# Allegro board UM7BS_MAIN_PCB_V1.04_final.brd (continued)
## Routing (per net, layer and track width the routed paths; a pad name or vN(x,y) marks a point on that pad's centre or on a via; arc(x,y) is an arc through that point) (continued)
GL850G_X1: length 7
  TOP w0.102: U9.6 180.29,89.43 C155.2 180.67,89.13 181.09,89.54 183.73,89.54 183.73,89.54 X4.1
GL850G_X2: length 5.4
  TOP w0.102: X4.3 182.97,90.21 182.51,89.75 181.1,89.75 C154.2 180.58,90.08 U9.7
GP_CAMERASB08: length 20.4
  TOP w0.102: U1.Y44 181.11,70.94 v1(180.74,71.31)
  LAY3 w0.102: v1(180.74,71.31) 180.36,71.69 180.36,74.18 181.63,75.45 181.63,76.22 182.38,76.97 182.38,77.92 188.13,83.67 v1(188.13,86.91)
  BOTTOM w0.152: R230.2 187.79,86.57 v1(188.13,86.91)
GP_CAMERASB09: length 23.7
  TOP w0.102: R228.1 188.22,88.44 189.28,87.38 189.28,86.69 188.98,86.39 v1(188.56,86.39) ; v1(180.74,70.68) 181.19,70.23 U1.Y42
  LAY3 w0.102: v1(188.56,86.39) 188.56,83.8 182.57,77.82 182.57,75.63 181.19,74.25 181.19,71.13 v1(180.74,70.68)
  BOTTOM w0.102: R232.2 181,70.94 v1(180.74,70.68)
GP_CAMERASB11: length 24.7
  TOP w0.102: v1(188.8,87) 188.8,87.53 188.4,87.93 R233.2 R229.1 ; U1.V40 180.27,68.8 v1(180.61,69.15)
  LAY3 w0.102: v1(188.8,87) 188.96,86.84 188.96,83.9 182.76,77.71 182.76,75.55 181.38,74.17 181.38,69.91 v1(180.61,69.15)
GPIO_SUS8: length 11.8
  TOP w0.102: 184.2,76.94 184.42,76.72 184.42,75.64 184.36,75.58 184.36,75.26 184.45,75.18 184.45,74.9 184.15,74.6 U1.AF51
  TOP w0.114: R68.1 182.69,84.34 182.3,83.95 182.3,82.48 R77.2 183.29,81.49 183.29,77.85 184.2,76.94
GPIO_SUS9: length 10.7
  TOP w0.102: U1.AF52 184.16,75.04 184.16,75.67 184.22,75.73 184.22,76.51 184,76.73
  TOP w0.114: 184,76.73 181.83,78.9 R76.1 181.27,82.57 181.27,83.69 R67.1
GPIO_SUS10: length 9.1
  TOP w0.102: 183.82,76.49 184.01,76.29 184.01,75.81 183.95,75.75 183.95,75.28 183.95,75.28 183.95,75.26 183.8,75.11 183.8,74.81 U1.AE51
  TOP w0.114: 183.82,76.49 181.29,79.02 181.29,80.95 R75.1 179.95,81.51 R66.2
GPIO_SUS11: length 7.5
  TOP w0.102: 182.29,76.3 182.39,76.2 182.39,75.27 182.7,74.96 U1.AC51
  TOP w0.114: 182.29,76.3 182.29,76.36 180.72,77.93 179.94,77.93 178.37,79.5 R78.2
GPO: length 2.7
  BOTTOM w0.114: R317.2 124.23,34.28 123.47,35.05 122.99,35.05 122.73,35.3 U22.38
H_PROCHOT#: length 145.4
  TOP w0.102: U33.4 51.04,64.6 C428.1 52.85,65.97 v1(53.48,66.6)
  TOP w0.114: U1.AD50 183.2,73.62 182.94,73.88 v1(182.75,73.88)
  LAY3 w0.102: v1(153.25,75.21) 151.12,77.34 112.64,77.34 111.22,75.92 103.19,75.92 101.38,74.1 80.25,74.1 79.38,74.97 73.85,74.97 v1(72.06,73.18)
  LAY4 w0.102: v1(53.48,66.6) 58.13,71.25 60.63,71.25 61.65,72.26 71.15,72.26 v1(72.06,73.18)
  BOTTOM w0.102: R108.1 182.25,75.1 180.62,75.1 180.12,75.61 175.86,75.61 174.65,76.82 174.65,78.36 173.67,79.33 169.88,79.33 169.14,78.59 158.91,78.59 155.52,75.21 v1(153.25,75.21)
  BOTTOM w0.114: R108.1 182.87,74 v1(182.75,73.88)
H_RCIN#: length 16.5
  TOP w0.102: v1(68.41,69.41) 69.56,68.25 72.21,68.25 73.08,69.12 74.66,69.12 v1(75.01,68.77)
  TOP w0.114: v1(75.01,68.77) 75.47,68.31 76.11,68.31 76.57,68.77 R412.2
  BOTTOM w0.102: v1(68.41,69.41) 67.79,70.02 D11.P
  BOTTOM w0.114: v1(75.01,68.77) 75.27,68.51 R414.1 75.55,68.13 76.06,67.63 U30.9 ; R431.1 65.87,70.79 66.64,70.02 D11.P
HD: length 35.9
  TOP w0.102: v1(179.6,47.56) 179.99,47.96 179.99,49.56 180.06,49.63 180.06,49.95 179.9,50.12 179.9,50.42 U1.U3
  TOP w0.114: v1(163.2,43.13) 161.8,44.53 161.8,48.79 160.98,49.61 158.11,49.61 v1(157.8,49.29) 157.84,49.25 U2.7 U4.7
  BOTTOM w0.102: v1(157.8,49.29) 157.67,49.17 R41.1
  BOTTOM w0.114: v1(163.2,43.13) 164.08,43.13 164.82,42.39 172.04,42.39 174.08,44.43 175.11,44.43 176.91,46.23 176.91,46.69 177.79,47.56 v1(179.6,47.56)
HDA_BITCLK: length 170.4
  TOP w0.114: v1(182.02,46.39) 181.31,45.68 180.73,45.68 177.88,42.83 166.32,42.83 165.36,43.78 165.36,44.8 163.75,46.41 163.75,49.09 161.52,51.33 159.82,51.33 158.89,52.26 156.22,52.26 155.17,51.21 126.69,51.21 124.86,49.39 115.52,49.39 112.66,46.53 110.39,46.53 109.41,45.55 100.37,45.55 98.56,43.74 93.39,43.74 87.94,38.29 81.01,38.29 80.76,38.03 66.36,38.03 64.37,36.04 42.45,36.04 42.22,36.28 33.2,36.28 32.6,35.68 v1(30.31,35.68)
  BOTTOM w0.114: v1(182.02,46.39) R31.2 ; v1(30.31,35.68) C389.2 29.67,35.04 U25.6
HDA_RST#: length 176.7
  TOP w0.102: v1(28.24,32.12) 28.24,32.14 29.29,33.19 30.59,33.19
  TOP w0.114: v1(183.35,45.78) 182.67,45.09 182.67,44.81 182.29,44.44 181.26,44.44 179.94,43.11 179.94,42.9 179.01,41.97 165.85,41.97 163.36,44.46 163.36,45.58 162.57,46.37 162.57,49.05 161.17,50.46 156.78,50.46 156.61,50.28 127.43,50.28 125.46,48.31 117.83,48.31 115.19,45.67 111.03,45.67 108.24,42.88 94.29,42.88 88.83,37.42 81.37,37.42 81.12,37.17 66.72,37.17 64.61,35.06 41.63,35.06 v1(41.5,35.2) 34.48,35.2 32.79,33.5 30.9,33.5 30.59,33.19
  BOTTOM w0.102: R358.1 39.98,37.53 40.44,37.08 R359.2 41.23,36.68 41.5,36.41 v1(41.5,35.2)
  BOTTOM w0.114: R30.2 v1(183.35,45.78) ; v1(28.24,32.12) 28.33,32.21 28.33,32.73 28.01,33.04 U25.11
HDA_SDATAIN0: length 175.2
  TOP w0.114: v1(181.87,45.55) 181.87,45.39 181.66,45.18 180.93,45.18 178.09,42.33 166.09,42.33 164.81,43.62 164.81,44.65 162.95,46.51 162.95,49.2 161.31,50.83 159.61,50.83 158.71,51.74 156.52,51.74 155.43,50.65 127.05,50.65 125.15,48.76 116.18,48.76 113.46,46.04 110.66,46.04 107.87,43.25 93.6,43.25 88.14,37.79 81.22,37.79 80.96,37.54 66.56,37.54 64.57,35.55 42.17,35.55 41.95,35.76 33.87,35.76 v1(32.57,34.47)
  BOTTOM w0.114: R32.2 181.4,49.41 181.4,46.02 v1(181.87,45.55) ; v1(32.57,34.47) 32.44,34.33 C391.2 31.89,33.37 29.54,33.37 28.67,34.24 U25.8
HDA_SDATAOUT: length 171.1
  TOP w0.114: v1(29.94,36.77) 42.47,36.77 42.7,36.54 64.16,36.54 66.15,38.53 80.55,38.53 80.81,38.78 87.73,38.78 93.18,44.24 95.7,44.24 98.58,47.12 99.46,47.12 100.53,46.05 109.11,46.05 110.1,47.04 112.46,47.04 115.37,49.94 124.62,49.94 126.4,51.72 154.92,51.72 155.97,52.77 159.07,52.77 160.02,51.82 161.72,51.82 164.3,49.25 164.3,46.57 167.54,43.32 177.68,43.32 180.53,46.18 181.1,46.18 181.96,47.03 v1(182.58,47.03)
  BOTTOM w0.114: v1(29.94,36.77) C392.2 29.11,35.44 U25.5 ; v1(182.58,47.03) 182.83,47.28 R34.2
HDA_SYNC: length 178.2
  TOP w0.102: 94.8,42.51 108.76,42.51 111.54,45.29 115.61,45.29 118.18,47.86 125.59,47.86 127.65,49.91 156.86,49.91
  TOP w0.114: 94.8,42.51 89.34,37.06 81.52,37.06 81.27,36.8 67.01,36.8 63.57,33.36 35.57,33.36 34.36,32.16 v1(34.36,31.65) ; v1(183.36,44.96) 183.36,44.93 180.43,42 179.78,42 179.38,41.6 165.59,41.6 162.98,44.21 162.98,45.41 162.18,46.21 162.18,48.93 161.02,50.09 157.03,50.09 156.86,49.91
  BOTTOM w0.114: U25.10 28.11,33.44 28.71,32.84 28.71,31.65 29.89,30.47 33.89,30.47 C390.2 34.36,30.59 v1(34.36,31.65) ; R33.2 184.94,45.04 184.7,44.79 183.53,44.79 v1(183.36,44.96)
HP_OUT_L: length 8.9
  TOP w0.305: R352.2 21.92,29.07 R356.1 21.92,29.38 C396.1 21.89,30.15 18.5,33.54 18.5,34.72 v1(18.34,34.88)
  BOTTOM w0.305: R332.1 18.35,34.89 v1(18.34,34.88)
HP_OUT_R: length 11.9
  TOP w0.305: v1(18.4,35.71) 18.93,35.19 18.93,33.81 21.29,31.44 22.75,31.44 23.86,30.33 R357.1 24.65,29.65 C397.1 24.82,29.66 R354.2
  BOTTOM w0.305: v1(18.4,35.71) 18.53,35.71 18.54,35.71 R331.1
HSON: length 4.6
  BOTTOM w0.124: U22.23 122.73,42.03 122.66,42.1 122.66,42.23 122.74,42.32 124.48,42.32 124.93,42.77 124.93,43.65 C346.2
HSOP: length 4.6
  BOTTOM w0.124: C347.2 124.68,43.65 124.68,42.87 124.38,42.57 122.64,42.57 122.4,42.34 122.4,42.1 122.33,42.03 U22.22
HUB_USB_PN1: length 131.5
  TOP w0.112: U9.2 v1(179.51,86.83)
  TOP w0.124: CN26.5 240.92,27.77 v1(241.03,27.67)
  LAY3 w0.112: v1(179.51,86.83) 179.51,86.92 179.83,87.24 181.45,87.24 187.15,92.94 195.48,92.94 199.62,97.08 203.74,97.08 205.57,98.91 210.39,98.91 212.47,100.98 213.53,100.98 214.06,100.46 218.66,100.46 227.42,91.7 227.42,47.79 240.1,35.11 240.1,28.06 240.41,27.75 240.95,27.75 v1(241.03,27.67)
HUB_USB_PN2: length 101.9
  TOP w0.124: v1(165.55,86.8) 165.73,86.63 170.77,86.63 170.97,86.83 U9.27
  LAY3 w0.112: v1(165.55,86.8) 165.34,86.6 163.53,86.6 158.88,91.24 151.87,91.24 149.31,93.8 119.31,93.8 117.44,91.92 111.64,91.92 110.97,91.25 96.33,91.25 95.26,92.32 85.85,92.32 82.92,95.26 77.44,95.26 v1(77.27,95.43)
  BOTTOM w0.124: v1(77.27,95.43) 77.1,95.25 76.7,95.25 76.58,95.37 U95.2
HUB_USB_PP1: length 131.6
  TOP w0.112: U9.3 179.49,87.48 v1(179.49,87.48)
  TOP w0.124: v1(241.03,28.28) 240.78,28.02 239.36,28.02 239.11,28.27 CN26.3
  LAY3 w0.112: v1(179.49,87.48) 181.35,87.48 187.05,93.18 195.38,93.18 199.52,97.32 203.64,97.32 205.47,99.15 210.29,99.15 212.37,101.22 213.63,101.22 214.16,100.7 218.75,100.7 227.66,91.8 227.66,47.89 240.34,35.21 240.34,28.16 240.51,27.99 240.74,27.99 v1(241.03,28.28)
HUB_USB_PP2: length 101.9
  TOP w0.124: v1(165.57,86.15) 165.8,86.38 170.77,86.38 170.97,86.18 U9.28
  LAY3 w0.112: v1(77.27,94.85) 77.44,95.02 82.82,95.02 85.75,92.09 95.16,92.09 96.23,91.02 111.07,91.02 111.74,91.69 117.54,91.69 119.41,93.56 149.21,93.56 151.77,91 158.78,91 163.43,86.36 165.36,86.36 v1(165.57,86.15)
  BOTTOM w0.124: U95.3 76.58,94.87 76.7,95 77.13,95 v1(77.27,94.85)
I2C_CLK0: length 2.9
  BOTTOM w0.114: R401.2 51.84,74.09 53.13,72.81 U31.110
I2C_CLK1: length 5.4
  BOTTOM w0.127: R423.2 54.38,76.05 54.38,74.63 R396.2 55.25,73.76 55.25,72.72 55.13,72.59 U31.115
I2C_CLK2: length 2.8
  BOTTOM w0.114: U31.117 55.93,72.46 56.92,73.45 R405.2
I2C_CLK2_LVDS: length 117.2
  LAY3 w0.127: v1(152.66,81.76) 152.16,81.25 123.29,81.25 122.13,82.4 116.5,82.4 115.74,83.17 58.31,83.17 54.89,79.75 v1(54.89,78.26)
  BOTTOM w0.102: U16.25 151.11,92.27 150.56,91.72 150.56,88.74 151.87,87.43 152.3,87.43 152.9,86.83 152.9,86.46 R276.2 152.66,85.75 153.06,85.35 153.06,82.16 v1(152.66,81.76) 152.03,82.4 U18.6
  BOTTOM w0.127: v1(54.89,78.26) 54.86,78.23 R423.1
I2C_CLK3: length 2.4
  BOTTOM w0.127: U31.94 45.43,69.46 44.95,69.94 R392.2
I2C_DATA0: length 2.7
  BOTTOM w0.114: U31.111 53.53,73.04 52.86,73.71 R402.2
I2C_DATA1: length 5.4
  BOTTOM w0.127: R424.2 55.4,76.09 55.4,74.63 R399.2 55.9,72.93 55.53,72.55 U31.116
I2C_DATA2: length 3.3
  BOTTOM w0.114: R408.2 57.94,73.58 57.75,73.4 57.41,73.4 56.33,72.32 U31.118
I2C_DATA2_LVDS: length 117.2
  LAY3 w0.127: v1(55.84,78.21) 55.84,80.1 58.62,82.87 115.53,82.87 116.25,82.16 121.77,82.16 123.31,80.62 145.95,80.62 146.35,80.22 151.75,80.22 v1(152.66,81.13)
  BOTTOM w0.102: U18.5 v1(152.66,81.13) 153.5,81.97 R277.2 153.25,86.47 153.25,86.86 152.41,87.69 151.98,87.69 150.82,88.85 150.82,91.61 151.51,92.29 U16.24
  BOTTOM w0.127: R424.1 55.84,78.21 v1(55.84,78.21)
I2C_DATA3: length 2.5
  BOTTOM w0.127: U31.95 45.69,69.86 44.82,70.73 R394.2
IINA: length 5.9
  BOTTOM w0.406: CN22.2 107.26,96.95 106.35,97.87 R3103.1 R3104.1 R3101.1 R3102.1
IINA0: length 26.6
  LAY3 w0.406: v1(113.26,95.59) 113.26,95.38 112.87,94.99 107.92,94.99 106.76,96.15 v1(103.73,96.15)
  BOTTOM w0.406: R3101.2 v1(103.73,96.15) ; v1(113.26,95.59) J5.1 115.85,94.33 R345.1 115.94,94.25 118.08,94.25 124.18,88.15 U41.1
IINA1: length 29.1
  LAY3 w0.406: v1(102.88,96.16) 103.43,96.71 107.13,96.71 108.25,95.59 v1(112.63,95.59)
  BOTTOM w0.406: R3102.2 v1(102.88,96.16) ; v1(112.63,95.59) 112.26,95.22 J5.2 112.26,93.52 112.75,93.03 115.5,93.03 R345.2 116.2,93.73 117.65,93.73 123.88,87.5 U41.2
IINA2: length 29.5
  LAY3 w0.406: v1(106.19,95.1) 107.44,93.84 113.89,93.84 114.86,94.81 v1(116.78,94.81)
  BOTTOM w0.406: U41.4 125.94,86.2 126.33,86.6 R3089.1 126.33,87.54 126.08,87.79 126.08,88.53 125.52,89.09 124.15,89.09 118.44,94.81 v1(116.78,94.81) ; v1(106.19,95.1) R367.2 R3095.1 105.56,96.82 R3103.2
IINA3: length 37
  LAY3 w0.406: v1(103.79,95.1) 104.33,95.64 106.4,95.64 107.59,94.45 113.66,94.45 114.59,95.38 v1(116.85,95.38)
  BOTTOM w0.406: v1(116.85,95.38) 118.96,95.38 124.55,89.78 126.8,89.78 128.16,88.42 R3090.1 128.16,85.8 127.92,85.55 U41.5 ; R3104.2 104.61,96.91 R3095.2 104.62,95.93 R3097.2 v1(103.79,95.1)
INNER_MIC: length 53.2
  TOP w0.305: B1.1 57.54,8.91 CN7.2 54.51,10.4 52.02,7.9 33.42,7.9 25.82,15.5 25.82,26.18 25.53,26.48 v1(25.53,26.79)
  BOTTOM w0.305: v1(25.53,26.79) 25.88,27.14 R333.2 25.7,27.69 C377.1 C373.1
IRQB: length 171
  TOP w0.102: R407.2 78.79,62.71 v1(79.08,63.01) ; Q52.2 151.5,16.75 v1(151.09,17.16)
  LAY3 w0.102: v1(149.48,59.71) 149.11,60.07 147.28,60.07 146.85,60.5 146.85,62.12 136.1,72.88 128.11,72.88 127.91,72.68 119.18,72.68 118.08,71.58 118.08,67.67 114.26,63.85 80.4,63.85 79.56,63.01 v1(79.08,63.01)
  LAY4 w0.102: v1(149.48,59.71) 149.25,59.47 149.25,52.69 153.58,48.36 154.07,48.36 155.2,47.22 v1(155.2,41.42) 155.2,40.61 155.59,40.23 155.59,36.45 158.25,33.79 158.25,28.6 158.49,28.37 158.49,26.84 158.21,26.56 158.21,19.84 156.95,18.58 155.1,18.58 154.43,19.25 151.79,19.25 151.09,18.55 v1(151.09,17.16)
  BOTTOM w0.102: v1(79.08,63.01) 78.93,63.16 U32.4
  BOTTOM w0.114: R569.1 180.75,50.03 178.8,48.08 177.59,48.08 176.45,46.94 176.45,46.51 175.43,45.49 174.34,45.49 171.76,42.91 165.21,42.91 164.28,43.84 161.3,43.84 159.7,42.24 156.02,42.24 v1(155.2,41.42)
ISETA: length 37.6
  TOP w0.305: 110.11,85.12 109.36,84.37 109.36,83.81 110.05,83.12 110.06,83.12 ; 110.11,85.12 CN40.6 112.61,85.12 R466.2 112.61,84.55 113.11,84.05 120.94,84.05 121.54,83.46 122.28,83.46 123.59,84.77 v1(126,84.77) ; 110.11,85.12 109.26,85.97 109.26,86.48 109.89,87.12 CN40.8 112.61,87.12 R3099.2 ; R465.2 111.11,83.11 CN40.4 110.06,83.12 ; R3098.2 111.11,81.11 CN40.2 110.02,81.12 109.35,81.79 109.35,82.4 110.06,83.12
  BOTTOM w0.305: R648.1 R638.2 R754.1 126.42,84.77 v1(126,84.77) 125.85,84.77 125.72,84.9 U41.6
ISOLATEB: length 3.2
  BOTTOM w0.114: R307.1 R305.1 125.37,40.89 124.89,40.4 U22.26
ISW: length 1.9
  BOTTOM w0.305: U41.10 118.05,84.25 117.39,83.6 R3091.2
IT8928_VSS: length 4.1
  BOTTOM w0.114: R452.1 49.59,72.7 50.57,72.7 50.73,72.54 U31.104
KBC_FAN_SPEED: length 107.7
  TOP w0.203: C1.2 129.67,10.1 Q1.3 ; C1.2 R584.2 ; C1.2 v1(129.67,13.76)
  LAY4 w0.102: v1(56.33,52.89) 62.15,52.89 63.39,54.14 64.12,54.14 66.31,51.95 94.32,51.95 96.9,49.37 105.6,49.37 107.73,47.24 107.73,39.92 108.66,38.99 108.66,35.98 110.04,34.6 111.55,34.6 119.14,27.01 119.14,18.23 121.24,16.13 127.02,16.13 129.39,13.76 v1(129.67,13.76)
  BOTTOM w0.102: R435.1 55.79,53.43 v1(56.33,52.89)
L_OUT+: length 7.5
  TOP w0.508: R362.1 242.16,14.64 242.75,15.22 242.75,16.75 242.26,17.24 CN10.2
L_OUT-: length 5
  TOP w0.508: CN10.1 240.94,15.6 R363.1
LAN_CMT: length 2
  TOP w0.406: R322.2 95.71,37.79 U23.11
LAN_CMT1: length 1.8
  BOTTOM w0.406: U24.11 95.92,35.24 R325.2
LAN_CT: length 1.7
  TOP w0.406: R321.2 95.99,33.98 U23.14
LAN_CT1: length 2
  BOTTOM w0.406: R323.2 95.71,39.05 U24.14
LAN_N1: length 23.6
  TOP w0.305: v1(92.47,35.78) 90.77,35.78 v1(90.27,35.28)
  TOP w0.406: R321.1 v1(95.04,34.59) 95.04,35.34 95.71,36 R322.1
  TOP w0.508: v1(95.93,21.99) 95.93,19.26 v1(95.97,19.22)
  BOTTOM w0.305: v1(92.47,35.78) R328.2 93.36,34.39 ; v1(90.27,35.28) 89.97,35.28 89.73,35.04 R329.2 ; R324.2 v1(95.97,19.22)
  BOTTOM w0.406: 95.71,36.83 R323.1
  BOTTOM w0.508: 95.25,28.53 96.53,27.25 96.53,22.48 96.05,21.99 v1(95.93,21.99) R327.2 ; 95.71,36.83 94.97,36.09 R325.1
LAN_TX0N: length 11.9
  TOP w0.102: U23.9 95.84,40.33 93.37,37.85 93.37,35.63 92.49,34.75 91.12,34.75 90.58,34.21 90.58,33.46 FIL1.1
LAN_TX0P: length 12.7
  TOP w0.102: FIL1.4 90.88,33.88 90.88,34.09 91.25,34.45 92.61,34.45 93.67,35.5 93.67,37.73 95.96,40.03 96.15,40.03 96.3,39.88 96.3,38.98 96.44,38.84 97.44,38.84 U23.10
LAN_TX1N: length 2.3
  TOP w0.102: FIL2.1 96.01,32.22 96.58,32.22 97.06,32.71 U23.15
LAN_TX1P: length 2.3
  TOP w0.102: FIL2.4 96.02,31.92 96.54,31.92 97.02,31.44 U23.16
LAN_TX2N: length 18
  BOTTOM w0.102: FIL3.4 94.46,21.04 R327.1 95.66,20.77 97.06,20.77 99.44,23.15 99.44,32.92 99.17,33.19 98.78,33.19 98.29,32.7 U24.9
LAN_TX2P: length 19
  BOTTOM w0.102: U24.10 98.3,33.97 98.78,33.49 99.29,33.49 99.74,33.04 99.74,23.03 97.18,20.47 95.67,20.47 R324.1 94.48,20.17 FIL3.1
LAN_TX3N: length 11.6
  BOTTOM w0.102: U24.15 97.04,40.32 96.56,40.81 95.95,40.81 91.25,36.11 91.25,34.66 R328.1 91.23,34.1 91.23,33.84 FIL4.1
LAN_TX3P: length 12.1
  BOTTOM w0.102: U24.16 97.06,41.59 96.58,41.11 95.83,41.11 90.95,36.23 90.95,34.67 R329.1 90.93,34.15 90.93,33.8 FIL4.4
LAN_VDDEN_EC: length 79.4
  LAY4 w0.102: v1(63.7,53.6) 65.64,51.66 94.15,51.66 96.66,49.15 105.53,49.15 107.53,47.15 107.53,39.69 108.36,38.86 108.36,35.76 109.3,34.82 109.3,33.97 v1(115.68,27.58)
  BOTTOM w0.102: R301.2 U21.3 114.67,28.15 115.23,27.58 v1(115.68,27.58)
  BOTTOM w0.114: U31.29 62.64,59.06 63.36,58.34 63.36,53.94 v1(63.7,53.6)
LANWAKEB: length 4.5
  BOTTOM w0.114: R304.1 128.21,39.49 125.12,39.49 125.01,39.6 U22.28
LAO1_CLKN: length 26
  BOTTOM w0.124: CN35.8 134.91,95.04 134.61,94.74 134.41,94.74 134.17,94.49 134.17,93.79 133.89,93.52 133.07,93.52 132.97,93.42 132.97,93.17 133.11,93.03 133.89,93.03 134.17,92.75 134.17,92.3 133.89,92.02 133.42,92.02 133.29,91.9 133.29,91.65 133.42,91.53 133.89,91.53 134.17,91.26 134.17,90.89 134.41,90.65 137.98,90.65 138.96,91.63 144.01,91.63 148.28,95.89 148.63,95.89 148.7,95.97 U16.35
LAO1_CLKP: length 26
  BOTTOM w0.124: CN35.9 133.91,93.9 133.79,93.77 132.97,93.77 132.71,93.52 132.71,93.06 133,92.77 133.79,92.77 133.91,92.65 133.91,92.4 133.79,92.28 133.31,92.28 133.04,92 133.04,91.55 133.31,91.28 133.79,91.28 133.91,91.15 133.91,90.79 134.31,90.4 138.09,90.4 139.07,91.38 144.12,91.38 148.38,95.64 148.59,95.64 148.66,95.57 U16.34
LAO1_DATAN0: length 30.7
  BOTTOM w0.124: U16.42 148.56,98.77 148.49,98.69 148.2,98.69 147.82,99.07 145.91,99.07 145.02,98.18 145.02,96.41 144.75,96.14 143.05,96.14 142.87,96.32 142.87,97 141.7,98.17 126.76,98.17 125.17,99.76 125.17,100.29 125.38,100.5 125.57,100.5 125.91,100.84 CN35.24
LAO1_DATAN1: length 21.4
  BOTTOM w0.124: U16.40 148.56,97.97 148.49,97.89 147.83,97.89 147.59,98.13 146.25,98.13 145.82,97.71 145.82,95.8 144.73,94.71 144.56,94.71 144.32,94.94 143.94,94.94 143.61,94.62 143.61,94.24 143.85,94 143.85,93.82 143.27,93.25 141.99,93.25 141.87,93.37 141.87,93.63 141.6,93.9 141.14,93.9 140.87,93.63 140.87,93.37 140.74,93.25 140.49,93.25 140.37,93.37 140.37,93.63 140.1,93.9 139.64,93.9 139.37,93.63 139.37,93.37 139.24,93.25 138.46,93.25 138.21,93.5 138.21,93.94 138.68,94.41 139.92,94.41 140.17,94.66 140.17,94.86 140.26,94.96 140.45,94.96 140.91,95.43 CN35.2
LAO1_DATAN2: length 21
  BOTTOM w0.124: CN35.5 137.91,95.12 137.59,94.79 137.39,94.79 137.17,94.57 137.17,93.42 136.79,93.04 136.03,93.04 135.71,92.72 135.71,92.06 136.02,91.75 137.51,91.75 138.18,92.42 143.73,92.42 148,96.69 148.49,96.69 148.56,96.77 U16.37
LAO1_DATAN3: length 24.7
  BOTTOM w0.124: U16.32 148.74,94.77 148.67,94.69 148.31,94.69 144.47,90.85 139.39,90.85 138.35,89.81 133.67,89.81 132.17,91.31 132.17,94.51 132.41,94.75 132.6,94.75 132.91,95.07 CN35.10
LAO1_DATAP0: length 30.7
  BOTTOM w0.124: CN35.23 124.91,100.17 124.92,100.16 124.92,99.65 126.65,97.92 141.59,97.92 142.62,96.89 142.62,96.21 142.94,95.89 144.85,95.89 145.27,96.3 145.27,98.07 146.02,98.82 147.72,98.82 148.09,98.44 148.49,98.44 148.56,98.37 U16.41
LAO1_DATAP1: length 21.4
  BOTTOM w0.124: U16.39 148.56,97.57 148.49,97.64 147.73,97.64 147.49,97.88 146.35,97.88 146.07,97.6 146.07,95.69 144.84,94.46 144.45,94.46 144.22,94.69 144.04,94.69 143.86,94.51 143.86,94.34 144.1,94.1 144.1,93.72 143.38,93 141.89,93 141.62,93.27 141.62,93.53 141.49,93.65 141.24,93.65 141.12,93.53 141.12,93.27 140.85,93 140.39,93 140.12,93.27 140.12,93.53 139.99,93.65 139.74,93.65 139.62,93.53 139.62,93.27 139.35,93 138.36,93 137.96,93.4 137.96,94.04 138.58,94.66 139.81,94.66 139.91,94.77 CN35.3
LAO1_DATAP2: length 21
  BOTTOM w0.124: CN35.6 136.91,93.52 136.68,93.29 135.93,93.29 135.46,92.82 135.46,91.95 135.92,91.49 137.61,91.49 138.29,92.17 143.83,92.17 148.11,96.44 148.49,96.44 148.56,96.37 U16.36
LAO1_DATAP3: length 24.7
  BOTTOM w0.124: U16.31 148.69,94.37 148.62,94.44 148.42,94.44 144.58,90.6 139.49,90.6 138.45,89.56 133.56,89.56 131.91,91.21 CN35.11
LAO_CLKN: length 24.6
  BOTTOM w0.124: U16.47 151.51,100.12 151.44,100.2 151.44,100.86 150.19,102.11 144.37,102.11 141.99,99.73 132,99.73 131.53,100.2 131.53,100.83 131.91,101.22 CN35.30
LAO_CLKP: length 24.6
  BOTTOM w0.124: U16.46 151.11,100.12 151.19,100.2 151.19,100.76 150.09,101.86 144.48,101.86 142.1,99.48 131.9,99.48 131.28,100.1 131.28,100.88 130.91,101.25 CN35.29
LAO_DATAN0: length 20.5
  LAY3 w0.112: v1(140.81,100.61) 140.54,100.88 140.54,101.18 140.85,101.49 148.34,101.49 149.01,100.82 154.37,100.82 154.98,101.43 154.98,101.74 v1(155.25,102.01)
  BOTTOM w0.124: CN35.39 140.91,100.71 v1(140.81,100.61) ; v1(155.25,102.01) 154.98,101.75 154.98,101.13 154.24,100.39 154.24,100.2 154.31,100.12 U16.54
LAO_DATAN1: length 24.2
  LAY3 w0.112: v1(153.99,103.21) 153.73,102.95 153.73,102.27 153.25,101.78 149.2,101.78 148.7,102.27 138.01,102.27 137.5,101.76 137.5,100.9 v1(137.77,100.63)
  BOTTOM w0.124: U16.52 153.51,100.12 153.44,100.2 153.44,100.66 153.73,100.95 153.73,102.95 v1(153.99,103.21) ; CN35.36 137.91,100.78 v1(137.77,100.63)
LAO_DATAN2: length 24.6
  LAY3 w0.112: v1(151.89,103.53) 151.62,103.26 151.62,102.94 151.3,102.62 149.68,102.62 148.73,103.57 134.67,103.57 134.52,103.43 134.52,103.23 v1(134.79,102.97)
  BOTTOM w0.124: CN35.33 134.91,102.84 v1(134.79,102.97) ; U16.49 152.31,100.07 152.24,100.14 152.24,101.59 151.63,102.21 151.63,103.27 v1(151.89,103.53)
LAO_DATAN3: length 26.3
  BOTTOM w0.124: CN35.27 128.91,100.8 128.54,100.43 128.54,99.82 129.42,98.93 142.34,98.93 144.47,101.06 149.79,101.06 150.24,100.61 150.24,100.2 150.31,100.12 U16.44
LAO_DATAP0: length 20.6
  LAY3 w0.112: v1(140.04,100.61) 140.3,100.88 140.3,101.28 140.75,101.72 148.44,101.72 149.11,101.06 154.27,101.06 154.74,101.53 154.74,101.74 v1(154.47,102.01)
  BOTTOM w0.124: U16.53 153.91,100.12 153.99,100.2 153.99,100.49 154.73,101.24 154.73,101.75 v1(154.47,102.01) ; CN35.38 139.91,100.73 v1(140.04,100.61)
LAO_DATAP1: length 24.2
  LAY3 w0.112: v1(136.99,100.63) 137.26,100.9 137.26,101.86 137.91,102.51 148.8,102.51 149.29,102.02 153.15,102.02 153.49,102.37 153.49,102.93 v1(153.22,103.21)
  BOTTOM w0.124: v1(136.99,100.63) 136.91,100.71 CN35.35 ; v1(153.22,103.21) 153.48,102.95 153.48,101.06 153.19,100.77 153.19,100.2 153.11,100.12 U16.51
LAO_DATAP2: length 24.6
  LAY3 w0.112: v1(134.02,102.97) 134.29,103.23 134.29,103.53 134.57,103.81 148.83,103.81 149.78,102.86 151.2,102.86 151.38,103.04 151.38,103.26 v1(151.11,103.53)
  BOTTOM w0.124: CN35.32 133.91,102.86 v1(134.02,102.97) ; U16.48 151.91,100.07 151.99,100.15 151.99,101.49 151.37,102.11 151.37,103.27 v1(151.11,103.53)
LAO_DATAP3: length 26.3
  BOTTOM w0.124: U16.43 149.91,100.12 149.99,100.2 149.99,100.5 149.68,100.81 144.57,100.81 142.45,98.68 129.32,98.68 128.29,99.71 128.29,100.43 127.91,100.8 CN35.26
LDO2-CAP: length 5.6
  BOTTOM w0.178: C376.2 20.66,40.7 20.66,39.89 21.85,38.7 22.83,38.7 23.43,38.11 U25.39
LDR: length 1.8
  BOTTOM w0.305: R606.1 117.45,84.48 117.88,84.9 U41.11
LL1: length 8.1
  BOTTOM w0.178: C165.2 123.64,61.92 123.48,61.76 U10.18
  BOTTOM w0.635: C165.2 124.67,61.92 125.87,63.12 v2(130.13,63.12)
LL2: length 14.3
  TOP w0.635: 115.26,72.67 115.26,68.89 117.67,66.48 117.67,63.03 v2(118.94,61.76)
  BOTTOM w0.254: v2(118.94,61.76) U10.8
  BOTTOM w0.381: C166.1 118.4,62.3 v2(118.94,61.76)
LPC_AD0: length 189.8
  TOP w0.102: U1.M3 177.35,50.59 177.06,50.3 177.06,50.04 177.14,49.95 177.14,48.45 176.27,47.58
  TOP w0.114: 176.27,47.58 176.27,46.66 175.78,46.17 170.26,46.17 169.64,46.79 168.84,46.79 168.01,47.62 168.01,50.04 163.19,54.86 161.28,54.86 158.8,57.35 150,57.35 149,56.35 138.61,56.35 137.55,55.29 123.9,55.29 121.45,52.84 111.67,52.84 110.11,51.28 105.68,51.28 105.34,51.62 105.34,66.46 103.43,68.38 98.04,68.38 88.43,58.77 84.21,58.77 82.67,60.31 74.01,60.31 71.74,62.59 66.51,62.59 63.92,65.17 63.92,66.39 63.8,66.5 63.22,66.5 63.11,66.61 63.11,68.24 62.89,68.45 60.78,68.45 60.64,68.31 60.64,67.51 60.37,67.25 v1(60.01,67.25) 59.63,67.63 56.95,67.63 53.38,64.06 53.38,58.44 49.48,54.54 49.48,45.9 v1(50.44,44.94)
  BOTTOM w0.102: U31.10 60.6,66.66 v1(60.01,67.25)
  BOTTOM w0.127: CN11.8 50.46,44.92 v1(50.44,44.94)
LPC_AD1: length 191.7
  TOP w0.102: 176.52,47.52 177.35,48.35 U1.M2
  TOP w0.114: v1(51.38,44.82) 51.38,45.04 50.58,45.84 50.58,54.87 53.94,58.23 53.94,64.07 57.12,67.25 v1(59.25,67.25) 59.85,66.65 60.96,66.65 61.08,66.76 61.08,67.97 61.19,68.08 61.42,68.08 61.53,67.97 61.53,66.76 61.65,66.65 61.88,66.65 61.99,66.76 61.99,67.97 62.1,68.08 62.33,68.08 62.45,67.97 62.45,66.29 66.43,62.31 71.55,62.31 73.76,60.09 81.69,60.09 83.24,58.55 88.52,58.55 98.13,68.16 103.34,68.16 105.13,66.37 105.13,51.53 105.59,51.06 110.3,51.06 111.86,52.62 121.92,52.62 124.23,54.93 137.51,54.93 138.7,56.12 149.26,56.12 150.22,57.08 158.7,57.08 161.2,54.58 163.17,54.58 167.76,49.98 167.76,47.56 168.75,46.58 169.47,46.58 170.09,45.95 175.97,45.95 176.52,46.51 176.52,47.52
  BOTTOM w0.102: U31.9 61.07,67.06 60.48,67.64 59.65,67.64 v1(59.25,67.25)
  BOTTOM w0.127: CN11.7 50.96,44.4 v1(51.38,44.82)
LPC_AD2: length 187.5
  TOP w0.102: 176.75,47.47 177.56,48.27 177.56,49.97 177.64,50.06 177.64,50.34 U1.N3
  TOP w0.114: 176.75,47.47 176.75,46.34 176.15,45.74 169.98,45.74 169.36,46.36 168.5,46.36 167.55,47.31 167.55,49.89 163.13,54.31 161.09,54.31 158.59,56.81 150.28,56.81 149.03,55.56 138.54,55.56 137.58,54.6 124.61,54.6 122.42,52.41 111.95,52.41 110.39,50.85 105.5,50.85 104.91,51.44 104.91,66.28 103.25,67.95 98.22,67.95 88.61,58.33 81.79,58.33 80.25,59.88 71.97,59.88 70.77,61.07 65.65,61.07 64.77,61.96 64.77,63.59 62.36,66 59.5,66 v1(59.19,66.31) 57.45,66.31 54.51,63.37 54.51,57.47 51.84,54.79 v1(51.84,45.26)
  BOTTOM w0.102: U31.8 60.95,67.46 60.57,67.85 59.23,67.85 58.79,67.41 58.79,66.7 v1(59.19,66.31)
  BOTTOM w0.127: CN11.6 51.46,43.99 51.84,44.37 v1(51.84,45.26)
LPC_AD3: length 186.7
  TOP w0.102: 176.98,47.39 177.84,48.25 U1.N1
  TOP w0.114: 176.98,47.39 176.98,46.11 176.39,45.52 169.86,45.52 169.23,46.14 168.29,46.14 167.27,47.17 167.27,49.86 163.08,54.05 160.99,54.05 158.49,56.55 150.38,56.55 149.04,55.21 138.68,55.21 137.72,54.25 124.78,54.25 122.72,52.19 112.04,52.19 110.48,50.63 105.41,50.63 104.7,51.35 104.7,66.19 103.16,67.73 98.31,67.73 88.7,58.12 81.7,58.12 80.16,59.66 71.66,59.66 70.49,60.83 65.52,60.83 64.42,61.92 64.42,63.54 62.44,65.52 58.88,65.52 v1(58.58,65.82) 57.79,65.82 55.33,63.36 55.33,55.86 52.41,52.94 v1(52.41,45.15)
  BOTTOM w0.102: v1(58.58,65.82) 58.58,67.49 59.14,68.05 60.65,68.05 60.84,67.86 U31.7
  BOTTOM w0.127: CN11.5 51.96,43.94 52.41,44.39 v1(52.41,45.15)
LPC_CLK_EC: length 184.3
  TOP w0.114: R85.1 177.69,45.43 177.06,44.8 169.55,44.8 169.21,45.13 168.3,45.13 166.44,46.99 166.44,49.68 162.83,53.3 160.63,53.3 159.07,54.86 152.02,54.86 150.41,53.24 125.29,53.24 123.53,51.48 112.33,51.48 110.77,49.92 105.12,49.92 103.99,51.05 103.99,65.83 102.8,67.02 98.61,67.02 88.99,57.41 85.02,57.41 84.29,56.67 81.79,56.67 79.65,58.81 71.44,58.81 70.64,59.61 65.73,59.61 63.71,61.63 63.71,62.98 62.15,64.54 58.63,64.54 v1(58.17,64.08) 56.82,62.72 56.82,55.33 54.66,53.18 54.66,46.06 52.44,43.84 v1(49.47,43.84)
  TOP w0.127: R87.1 178,45.93 R85.1
  BOTTOM w0.114: v1(58.17,64.08) 59.55,65.46 U31.13
  BOTTOM w0.127: CN11.10 49.46,43.83 v1(49.47,43.84)
LPC_CLKRUN#: length 204.1
  TOP w0.102: U1.T3 179.29,50.61 179.6,50.31 179.6,50.07 179.59,50.07 179.59,50.06 179.5,49.97 179.5,49.6 179.57,49.52 179.57,48.81 179.47,48.71 ; 53.16,43.13 53.59,43.13 57.45,47 57.45,49.21
  TOP w0.114: 179.47,48.71 179.19,48.43 179.19,47.3 179.51,46.99 179.51,45.86 177.47,43.82 168.19,43.82 165.15,46.87 165.15,49.59 164.11,50.63 163.62,50.63 161.93,52.32 160.23,52.32 158.88,53.67 154.79,53.67 153.35,52.23 125.99,52.23 124.26,50.5 112.74,50.5 111.18,48.94 104.71,48.94 103.01,50.65 103.01,65.43 102.39,66.04 99.01,66.04 89.4,56.43 86.58,56.43 85.42,55.27 79.88,55.27 79.21,55.93 79.21,57.81 78.74,58.28 75.05,58.28 74.49,57.71 71.83,57.71 70.95,58.58 67.77,58.58 63.12,53.93 62.17,53.93 57.45,49.21 ; v1(43.84,52.28) 43.84,47.47 48.18,43.13 53.16,43.13
  LAY3 w0.102: v1(43.36,68.54) 43.84,68.06 v1(43.84,52.28)
  BOTTOM w0.102: R411.2 v1(43.36,68.54)
LPC_FRAME#: length 190.3
  TOP w0.102: 177.2,47.28 178.12,48.2 178.12,49.97 178.03,50.06 178.03,50.3 178.32,50.59 U1.P3
  TOP w0.114: v1(49.96,44.43) 52.32,44.43 54.06,46.18 54.06,53.5 56.12,55.56 56.12,63.25 v1(58.06,65.19) 59.75,65.19 59.85,65.08 62.35,65.08 64.21,63.22 64.21,61.84 65.5,60.54 70.45,60.54 71.67,59.32 80.19,59.32 81.61,57.9 88.79,57.9 98.4,67.52 103.07,67.52 104.48,66.11 104.48,51.26 105.32,50.42 110.57,50.42 112.13,51.98 123.19,51.98 124.95,53.74 150.16,53.74 152.44,56.02 158.61,56.02 160.84,53.79 163.03,53.79 166.94,49.89 166.94,47.2 168.2,45.93 169.14,45.93 169.78,45.29 176.61,45.29 177.2,45.88 177.2,47.28
  BOTTOM w0.114: U31.6 58.96,68.26 58.06,67.36 v1(58.06,65.19)
  BOTTOM w0.127: v1(49.96,44.43) 49.96,44.43 CN11.9
LPC_SERIRQ: length 150.5
  TOP w0.102: 179.29,48.96 179.37,49.03 179.37,49.44 179.29,49.51 U1.T2 ; 178.95,46 177.26,44.31 168.4,44.31 165.64,47.07 165.64,49.8 164.08,51.35 163.58,51.35 162.13,52.81 160.43,52.81 159.01,54.23 152.27,54.23 150.8,52.75 125.68,52.75 123.92,50.99 112.54,50.99 110.98,49.43 104.91,49.43 103.5,50.85 103.5,65.63 102.59,66.53 98.81,66.53 89.19,56.92 85.23,56.92 84.49,56.18 80.74,56.18 80.58,56.03 80.05,56.03 v1(79.78,56.3)
  TOP w0.114: 179.29,48.96 178.95,48.61 178.95,46
  LAY3 w0.102: v1(79.78,56.3) 79.78,58.11 78.17,59.72 78.17,67.74 v1(79.04,68.61) 79.04,69.77 v1(78.64,70.18)
  BOTTOM w0.102: U29.3 79.08,71.81 78.64,71.37 R390.1 v1(78.64,70.18)
  BOTTOM w0.114: v1(79.04,68.61) 78.46,68.03 U30.2
LPC_SERIRQ_EC: length 58.6
  TOP w0.114: v1(60.3,69.48) 57.92,69.48 52.91,64.47 52.91,58.61 48.46,54.15 v1(48.46,45.03)
  LAY3 w0.102: v1(75.68,68.77) 75.68,71.21 v1(75.48,71.41)
  LAY4 w0.102: v1(75.48,71.41) 65.32,71.41 63.38,69.47 60.31,69.47 v1(60.3,69.48)
  BOTTOM w0.102: R390.2 77.69,71.08 77.44,71.33 U29.4
  BOTTOM w0.114: v1(75.68,68.77) 75.68,68.51 76.17,68.03 U30.10 ; U31.5 60.82,68.66 60.3,69.17 v1(60.3,69.48) ; U29.4 76.77,71.81 76.38,71.41 v1(75.48,71.41) ; CN11.12 v1(48.46,45.03)
LPCPD#: length 19.3
  TOP w0.102: R440.2 76.59,61.42 v1(76.13,61.88) 76.07,61.88 75.69,61.5 73.85,61.5 72.51,62.84 66.61,62.84 65.56,63.89 v1(65.56,64.44)
  BOTTOM w0.102: R441.1 76.57,61.88 v1(76.13,61.88)
  BOTTOM w0.114: U31.17 62.69,63.86 63.45,64.62 65.38,64.62 v1(65.56,64.44) ; U32.7 76.66,62.76 76.13,62.23 v1(76.13,61.88)
LX3: length 1.6
  TOP w0.178: U11.10 155.61,21.59
  TOP w0.203: 155.61,21.59 155.58,21.55
LX4: length 2.8
  TOP w0.178: U11.25 161.24,17.29 161.54,16.98
  TOP w0.508: 161.88,11.84 R840.2
LX5: length 2.5
  TOP w0.178: 159.24,17.34 U11.20
  TOP w0.203: 159.13,17.23 159.24,17.34
  TOP w0.406: 157.8,11.8 157.01,11.01 R841.2
M_A_A0: length 36.5
  TOP w0.102: U1.BB47 192.11,72.58 v1(192.55,72.58)
  TOP w0.203: CN1.98 v1(218.58,69.85)
  LAY3 w0.102: 193.44,74.49 192.9,73.95 192.9,73.32 192.55,72.96 v1(192.55,72.58)
  LAY3 w0.203: v1(218.58,69.85) 218.64,69.85 219.22,70.43 219.22,72.96 218.66,73.52 213.33,73.52 209.44,77.41 197.27,77.41 194.86,75 193.95,75 193.44,74.49
M_A_A1: length 37.1
  TOP w0.102: U1.BC42 192.63,70.13 v1(192.63,70.42)
  TOP w0.203: CN1.97 213.61,70.15 v1(214.77,71.31)
  LAY3 w0.102: 198.51,73.99 198.25,73.73 196.23,73.73 195.22,72.71 195.22,71.82 194.45,71.06 193.26,71.06 v1(192.63,70.42)
  LAY3 w0.203: 198.51,73.99 198.88,74.36 202.26,74.36 202.44,74.54 202.44,75.07 202.62,75.25 204.87,75.25 205.76,74.36 208.93,74.36 213,70.3 213.38,70.3 213.76,70.68 214.01,70.68 214.39,70.3 216.35,70.3 216.55,70.5 216.55,71.74 216.35,71.95 215.74,71.95 215.54,71.74 215.54,71.26 215.33,71.06 215.03,71.06 v1(214.77,71.31)
M_A_A2: length 29.6
  TOP w0.102: v1(197.38,74.11) 196.3,73.03 195.61,73.03 U1.BJ48
  TOP w0.203: CN1.96 v1(218.58,70.45)
  LAY3 w0.203: v1(197.38,74.11) 197.38,75.76 197.88,76.27 208.86,76.27 213.05,72.07 215.03,72.07 215.41,72.46 216.57,72.46 v1(218.58,70.45)
M_A_A3: length 27.5
  TOP w0.102: v1(198.01,74.11) 196.73,72.83 195.98,72.83 195.71,72.56 195,72.56 U1.BH47
  TOP w0.203: CN1.95 212.68,70.75 v1(213.25,71.31)
  LAY3 w0.203: v1(213.25,71.31) 212.87,71.31 209.19,75 206.14,75 205.38,75.76 202,75.76 201.82,75.58 201.82,75.17 201.64,75 201.39,75 201.21,75.17 201.21,75.58 201.03,75.76 200.78,75.76 200.6,75.58 200.6,75.17 200.42,75 200.17,75 199.99,75.17 199.99,75.58 199.81,75.76 199.56,75.76 199.38,75.58 199.38,75.17 199.21,75 198.95,75 198.77,75.17 198.77,75.58 198.6,75.76 198.14,75.76 198.01,75.63 v1(198.01,74.11)
M_A_A4: length 37.2
  TOP w0.102: v1(193.18,70.43) 193.13,70.38 U1.BD42
  TOP w0.203: v1(217.06,70.45) 218.26,71.65 CN1.92
  LAY3 w0.102: v1(193.18,70.43) 193.19,70.43 193.59,70.83 194.61,70.83 195.6,71.82 195.6,72.58 196.38,73.36 198.66,73.36 198.81,73.51
  LAY3 w0.203: v1(217.06,70.45) 217.06,70.17 217.26,69.97 217.87,69.97 218.08,69.76 218.08,69.41 217.87,69.2 216.37,69.2 215.79,69.79 212.74,69.79 208.68,73.85 204.97,73.85 204.79,74.03 204.79,74.56 204.61,74.74 204.36,74.74 204.18,74.56 204.18,74.03 204,73.85 203.75,73.85 203.57,74.03 203.57,74.56 203.39,74.74 203.14,74.74 202.96,74.56 202.96,74.03 202.78,73.85 199.15,73.85 198.81,73.51
M_A_A5: length 31.3
  TOP w0.102: U1.BH48 195.07,73.23 195.86,73.23 v1(196.74,74.11)
  TOP w0.203: CN1.91 214.17,71.95 v1(214.77,72.55)
  LAY4 w0.203: v1(196.74,74.11) 197.25,74.61 205.88,74.61 206.39,74.11 211.6,74.11 212.46,73.25 216.93,73.25 217.19,73 217.19,71.77 216.98,71.57 215.28,71.57 214.77,72.07 v1(214.77,72.55)
M_A_A6: length 32.6
  TOP w0.102: v1(192.55,71.97) 192.22,71.97 U1.BB46
  TOP w0.203: CN1.90 v1(218.58,72.25)
  LAY3 w0.102: 194.78,73.28 194.58,73.09 193.95,73.09 193.67,72.81 193.34,72.81 192.55,72.02 v1(192.55,71.97)
  LAY3 w0.203: 194.78,73.28 195.09,73.6 195.09,74.49 197.5,76.9 209.19,76.9 213.07,73.01 216.88,73.01 217.57,72.33 218.5,72.33 v1(218.58,72.25)
M_A_A7: length 36
  TOP w0.102: U1.BE46 193.66,71.68 v1(193.66,71.47)
  TOP w0.203: v1(217.82,72.85) 218.42,73.45 CN1.86
  LAY4 w0.102: v1(193.66,71.47) 194.21,72.02 194.78,72.02 195.47,72.71
  LAY4 w0.203: v1(217.82,72.85) 217.82,71.19 217.57,70.93 216.55,70.93 216.36,70.74 216.36,70.23 216.17,70.04 215.77,70.04 215.6,70.22 215.6,70.63 215.42,70.8 215.16,70.8 214.99,70.63 214.99,70.22 214.81,70.04 214.56,70.04 214.38,70.22 214.38,70.63 214.2,70.8 213.95,70.8 213.77,70.63 213.77,70.22 213.59,70.04 213,70.04 212.52,70.52 212.52,71.13 212.34,71.31 212.09,71.31 211.91,71.13 211.91,70.73 211.73,70.55 211.48,70.55 211.3,70.73 211.3,71.13 211.12,71.31 210.08,71.31 209.31,72.07 204.56,72.07 204.36,72.28 204.36,73.22 204.11,73.47 199.15,73.47 198.77,73.09 195.85,73.09 195.47,72.71
M_A_A8: length 35.3
  TOP w0.102: U1.BD44 193.12,71.5 v1(193.11,71.52)
  TOP w0.203: CN1.89 v1(213.25,72.55)
  LAY4 w0.102: v1(193.11,71.52) 193.54,71.95 193.69,71.95 194.02,72.28 194.66,72.28 194.84,72.46 194.84,72.84 195.09,73.09
  LAY4 w0.203: v1(213.25,72.55) 213.38,72.42 213.38,71.95 213.25,71.82 212.84,71.82 212.64,72.02 212.64,72.53 212.46,72.71 212.21,72.71 212.03,72.53 212.03,72.02 211.83,71.82 211.55,71.82 211.35,72.02 211.35,73.34 211.09,73.6 210.77,73.6 210.59,73.42 210.59,72.13 210.41,71.95 210.16,71.95 209.98,72.13 209.98,73.42 209.81,73.6 209.55,73.6 209.37,73.42 209.37,72.89 209.2,72.71 208.94,72.71 208.77,72.89 208.77,73.42 208.59,73.6 208.33,73.6 208.16,73.42 208.16,73.02 207.98,72.84 207.73,72.84 207.55,73.02 207.55,73.42 207.37,73.6 207.12,73.6 206.94,73.42 206.94,73.02 206.76,72.84 206.51,72.84 206.33,73.02 206.33,73.42 206.15,73.6 205.9,73.6 205.72,73.42 205.72,73.02 205.54,72.84 205.29,72.84 205.11,73.02 205.11,73.99 205,74.11 199.03,74.11 198.47,73.55 195.55,73.55 195.09,73.09
M_A_A9: length 32
  TOP w0.102: v1(195.47,77.15) 194.2,77.15 193.69,76.65 193.69,76.01 193.31,75.63 193.31,75.22 U1.BE52
  TOP w0.203: CN1.85 214.17,73.75 v1(214.77,74.35)
  LAY3 w0.203: v1(195.47,77.15) 196.23,77.92 209.69,77.92 211.35,76.27 215.78,76.27 216.17,75.87 216.17,74.55 215.97,74.35 v1(214.77,74.35)
M_A_A10: length 25.6
  TOP w0.102: U1.BJ45 197.04,71.35 v1(198.01,72.33)
  TOP w0.203: CN1.107 212.89,67.15 213.25,67.5 v1(213.25,67.75)
  LAY3 w0.102: v1(198.01,72.33) 198.39,72.71 198.9,72.71 199.03,72.58 199.28,72.58
  LAY3 w0.203: v1(213.25,67.75) 208.41,72.58 208.04,72.58 207.86,72.4 207.86,72 207.68,71.82 207.43,71.82 207.25,72 207.25,72.4 207.07,72.58 206.82,72.58 206.64,72.4 206.64,72 206.46,71.82 206.21,71.82 206.03,72 206.03,72.4 205.85,72.58 205.6,72.58 205.42,72.4 205.42,72 205.24,71.82 204.99,71.82 204.81,72 204.81,72.4 204.63,72.58 199.28,72.58
M_A_A11: length 34.7
  TOP w0.102: U1.BB49 192.18,73.15 v1(192.52,73.5)
  TOP w0.203: CN1.84 v1(218.58,74.05)
  LAY4 w0.102: v1(192.52,73.5) 192.93,73.9 192.93,73.98 193.82,74.87 193.82,77.03 194.33,77.54
  LAY4 w0.203: 194.33,77.54 194.96,78.17 216.43,78.17 219.09,75.5 219.09,74.55 v1(218.58,74.05)
M_A_A12: length 32.8
  TOP w0.102: U1.BF48 193.91,72.77 v1(193.47,73.21)
  TOP w0.203: CN1.83 v1(213.25,74.35)
  LAY4 w0.102: v1(193.47,73.21) 193.69,73.43 193.69,73.73 194.2,74.23
  LAY4 w0.203: v1(213.25,74.35) 212.16,75.43 211.04,75.43 210.46,76.01 208.43,76.01 208.25,76.19 208.25,76.47 208.07,76.65 207.82,76.65 207.64,76.47 207.64,76.19 207.46,76.01 207.21,76.01 207.03,76.19 207.03,76.47 206.85,76.65 206.6,76.65 206.42,76.47 206.42,76.19 206.24,76.01 205.99,76.01 205.81,76.19 205.81,76.47 205.63,76.65 205.38,76.65 205.2,76.47 205.2,76.19 205.02,76.01 204.77,76.01 204.59,76.19 204.59,76.47 204.41,76.65 204.16,76.65 203.98,76.47 203.98,76.19 203.8,76.01 203.55,76.01 203.37,76.19 203.37,76.47 203.19,76.65 202.94,76.65 202.76,76.47 202.76,76.19 202.58,76.01 202.33,76.01 202.15,76.19 202.15,76.47 201.98,76.65 201.72,76.65 201.54,76.47 201.54,76.19 201.37,76.01 201.11,76.01 200.94,76.19 200.94,76.47 200.76,76.65 200.5,76.65 200.33,76.47 200.33,76.19 200.15,76.01 199.89,76.01 199.72,76.19 199.72,76.47 199.54,76.65 199.29,76.65 199.11,76.47 199.11,76.19 198.93,76.01 198.68,76.01 198.5,76.19 198.5,76.47 198.32,76.65 198.07,76.65 197.89,76.47 197.89,76.19 197.71,76.01 197.46,76.01 197.28,76.19 197.28,76.47 197.1,76.65 196.85,76.65 196.67,76.47 196.67,76.19 196.49,76.01 196.23,76.01 195.85,75.63 194.96,75.63 194.58,75.25 194.58,74.61 194.2,74.23
M_A_A13: length 35.3
  TOP w0.102: v1(194.23,71.47) 194.23,71.36 193.84,70.97 U1.BF44
  TOP w0.203: CN1.119 214.16,63.55 v1(214.77,62.93)
  LAY4 w0.203: v1(214.77,62.93) 216.1,62.93 216.3,63.13 216.3,63.87 216.5,64.07 217.75,64.07 217.95,64.28 217.95,64.63 217.75,64.84 215.54,64.84 215.28,64.58 211.85,64.58 209.82,66.61 206.39,66.61 201.44,71.57 194.33,71.57 v1(194.23,71.47)
M_A_A14: length 29.8
  TOP w0.102: U1.BD47 193.4,72.32 v1(193.49,72.4)
  TOP w0.203: CN1.80 218.26,75.25 v1(217.06,74.05)
  LAY4 w0.102: v1(193.49,72.4) 193.67,72.58 193.82,72.58 195.09,73.85
  LAY4 w0.203: v1(217.06,74.05) 216.79,73.78 216.37,73.78 215.92,74.23 215.61,74.23 215.16,73.78 212.69,73.78 211.73,74.74 206.77,74.74 206.27,75.25 197.25,75.25 196.54,74.54 195.78,74.54 195.09,73.85
M_A_A15: length 32.6
  TOP w0.102: v1(193.31,73.75) 192.97,73.41 U1.BD49
  TOP w0.203: CN1.78 v1(217.82,75.85)
  LAY4 w0.102: v1(193.31,73.75) 193.31,73.85 194.07,74.61 194.07,76.7 194.68,77.31
  LAY4 w0.203: 194.68,77.31 195.04,77.66 210.46,77.66 211.57,76.55 215.59,76.55 215.75,76.7 215.75,77.36 215.92,77.54 216.18,77.54 216.36,77.36 216.36,76.7 216.53,76.52 217.15,76.52 v1(217.82,75.85)
M_A_BS0: length 33.5
  TOP w0.102: U1.BH46 196.28,71.87 v1(196.74,72.33)
  TOP w0.203: CN1.109 213.57,66.55 v1(214.77,67.75)
  LAY3 w0.102: v1(196.74,72.33) 197.38,72.96 198.9,72.96 199.03,73.09 199.35,73.09
  LAY3 w0.203: 199.35,73.09 205.5,73.09 205.76,73.35 206.39,73.35 206.65,73.09 207.15,73.09 207.41,73.35 207.92,73.35 208.17,73.09 208.68,73.09 213.12,68.65 217.24,68.65 217.44,68.44 217.44,67.95 217.24,67.75 217.06,67.75 216.88,67.57 216.88,67.05 216.7,66.87 216.45,66.87 216.27,67.05 216.27,67.57 216.09,67.75 v1(214.77,67.75)
M_A_BS1: length 37.5
  TOP w0.102: U1.AY40 191,68.96 v1(191.35,69.31)
  TOP w0.203: v1(217.82,67.45) 218.42,66.85 CN1.108
  LAY3 w0.102: v1(191.35,69.31) 192.08,70.04 194.2,70.04 195.98,71.82 196.55,71.82
  LAY3 w0.203: v1(217.82,67.45) 218.15,67.12 219.02,67.12 219.22,66.92 219.22,66.56 219.02,66.36 215.73,66.36 215.56,66.54 215.56,66.94 215.38,67.12 215.12,67.12 214.95,66.94 214.95,66.54 214.77,66.36 214.47,66.36 214.27,66.56 214.27,66.92 214.06,67.12 213.12,67.12 209.44,70.8 204.87,70.8 203.85,71.82 196.55,71.82
M_A_BS2: length 30.2
  TOP w0.102: U1.BF52 194.1,75.05 194.1,75.55 194.68,76.14 v1(194.71,76.14)
  TOP w0.203: CN1.79 v1(213.25,75.55)
  LAY4 w0.203: v1(194.71,76.14) 195.22,76.65 196.11,76.65 196.61,77.15 210.08,77.15 211.19,76.04 216.35,76.04 216.55,75.83 216.55,75.2 216.35,75 213.8,75 v1(213.25,75.55)
M_A_CAS#: length 27.4
  TOP w0.102: U1.BG45 194.99,71.31 195.33,71.64 196.69,71.64 v1(197.38,72.33)
  TOP w0.203: CN1.115 214.18,64.75 v1(214.77,65.34)
  LAY4 w0.102: 199.28,72.84 197.88,72.84 v1(197.38,72.33)
  LAY4 w0.203: v1(214.77,65.34) 212.49,67.63 212.49,68.14 210.08,70.55 204.74,70.55 202.46,72.84 199.28,72.84
M_A_DM0: length 52.1
  TOP w0.102: U1.AP52 188.04,75.66 188.28,75.9 188.28,77.49 v1(187.85,77.92)
  TOP w0.127: v1(214.77,97.15) 213.57,98.35 CN1.11
  BOTTOM w0.127: v1(214.77,97.15) 214.34,96.71 212.74,96.71 212.23,96.2 212.23,94.63 210.84,93.23 210.84,89.75 210.69,89.6 210.48,89.6 210.33,89.75 210.33,92.11 210.17,92.27 209.95,92.27 209.81,92.13 209.81,88.7 208.68,87.57 194.13,87.57 189.78,83.21 189.78,81.89 187.85,79.96 v1(187.85,77.92)
M_A_DM1: length 50.2
  TOP w0.114: U1.AT48 188.61,73.46 v1(188.5,73.46)
  TOP w0.127: CN1.28 218.42,93.25 v1(217.82,93.85)
  LAY4 w0.127: v1(217.82,93.85) 217.82,92.72 217.62,92.52 216.76,92.52 216.55,92.72 216.55,94.81 216.04,95.32 213,95.32 212.36,95.95 210.33,95.95 203.73,89.35 198.26,89.35 187.16,78.25 187.16,76.06 187.72,75.5 187.72,74.23 v1(188.5,73.46)
M_A_DM2: length 50.2
  TOP w0.102: v1(188.51,71.01) 188.44,70.94 U1.AP44
  TOP w0.127: CN1.46 218.42,87.85 v1(217.82,87.25)
  LAY3 w0.102: v1(188.51,71.01) 188.1,71.41 188.1,74.87 188.36,75.12
  LAY3 w0.127: v1(217.82,87.25) 216.18,88.89 212.03,88.89 209.31,86.17 208.83,86.17 208.68,86.02 208.68,85.61 208.53,85.46 208.32,85.46 208.17,85.61 208.17,86.02 208.02,86.17 207.81,86.17 207.66,86.02 207.66,85.05 207.51,84.9 207.3,84.9 207.16,85.05 207.16,86.02 207.01,86.17 206.8,86.17 206.65,86.02 206.65,85.05 206.5,84.9 206.29,84.9 206.14,85.05 206.14,86.02 205.99,86.17 196.61,86.17 188.87,78.42 188.87,75.63 188.36,75.12
M_A_DM3: length 36
  TOP w0.102: U1.BA53 191.46,75.44 191.46,76.35 v1(191.84,76.72)
  TOP w0.127: v1(213.25,82.75) CN1.63
  BOTTOM w0.127: v1(213.25,82.75) 213.25,82.74 203.24,82.74 203.12,82.86 203.12,83.12 202.99,83.25 202.8,83.25 202.66,83.12 202.66,82.86 202.55,82.75 202.32,82.75 202.2,82.86 202.2,83.26 202.09,83.38 201.86,83.38 201.75,83.26 201.75,82.86 201.63,82.75 201.4,82.75 201.29,82.86 201.29,83.26 201.18,83.38 200.95,83.38 200.83,83.26 200.83,82.86 200.72,82.75 200.49,82.75 200.38,82.86 200.38,83.26 200.26,83.38 200.03,83.38 199.92,83.26 199.92,82.86 199.8,82.75 199.58,82.75 199.46,82.86 199.46,83.26 199.35,83.38 199.12,83.38 199,83.26 199,82.86 198.89,82.75 198.66,82.75 198.55,82.86 198.55,83.26 198.43,83.38 198.2,83.38 198.09,83.26 198.09,82.86 197.98,82.75 197.75,82.75 197.63,82.86 197.63,83.26 197.52,83.38 197.29,83.38 197.18,83.26 197.18,82.86 197.06,82.75 196.83,82.75 196.72,82.86 196.72,83.26 196.6,83.38 196.18,83.38 191.91,79.11 191.91,78.68 191.41,78.17 191.41,77.15 v1(191.84,76.72)
M_A_DM4: length 31.3
  TOP w0.102: U1.BG41 194.87,69.28 195.17,69.28 195.32,69.13 196.2,69.13 196.55,68.77 197.83,68.77 v1(198.65,67.96)
  TOP w0.127: CN1.136 218.42,58.45 v1(217.82,59.05)
  BOTTOM w0.127: v1(198.65,67.96) 198.72,67.88 200.45,67.88 200.75,67.59 202.2,67.59 205.84,63.95 208.93,63.95 210.33,62.55 210.33,60.78 210.76,60.34 214.34,60.34 215.03,59.65 215.41,59.65 216.45,58.61 217.62,58.61 217.82,58.82 v1(217.82,59.05)
M_A_DM5: length 41.6
  TOP w0.114: v1(191.28,67.48) 191,67.2 U1.AY36
  TOP w0.127: CN1.153 213.29,53.35 v1(213.89,53.95)
  LAY3 w0.102: v1(191.28,67.48) 192.27,66.49 195.34,66.49 195.75,66.08
  LAY3 w0.127: 195.75,66.08 200.32,66.08 209,57.41 209.98,57.41 210.1,57.28 210.1,56.35 210.25,56.2 210.46,56.2 210.61,56.35 210.61,57.28 210.74,57.41 210.99,57.41 211.12,57.28 211.12,55.46 211.27,55.31 211.48,55.31 211.63,55.46 211.63,57.28 211.75,57.41 212.04,57.41 212.23,57.22 212.23,54.17 212.36,54.04 212.62,54.04 212.74,54.17 212.74,54.8 212.87,54.93 214.37,54.93 214.52,54.78 214.52,54.57 214.37,54.42 214.09,54.42 213.89,54.22 v1(213.89,53.95)
M_A_DM6: length 44.1
  TOP w0.102: v1(193.44,64.58) 193.44,64.74 U1.BD32
  TOP w0.127: CN1.170 218.42,48.25 v1(217.82,48.85)
  LAY4 w0.102: 194.58,64.2 193.82,64.2 v1(193.44,64.58)
  LAY4 w0.127: v1(217.82,48.85) 217.82,48.2 217.47,47.84 209.03,47.84 208.42,48.45 208.42,49.08 208.3,49.21 207.81,49.21 207.66,49.35 207.66,49.56 207.81,49.71 208.3,49.71 208.42,49.84 208.42,50.09 208.3,50.22 207.81,50.22 207.66,50.37 207.66,50.58 207.81,50.73 208.3,50.73 208.42,50.86 208.42,51.11 208.3,51.24 207.81,51.24 207.66,51.39 207.66,51.6 207.81,51.75 208.3,51.75 208.42,51.87 208.42,52.13 208.3,52.25 207.81,52.25 207.66,52.4 207.66,52.61 207.81,52.76 208.3,52.76 208.42,52.89 208.42,55.56 200.27,63.72 195.83,63.72 195.34,64.2 194.58,64.2
M_A_DM7: length 38.9
  TOP w0.102: U1.BH30 195.77,64.07 196.1,63.73 197.42,63.73 v1(198.01,64.33)
  TOP w0.127: v1(214.01,43.75) 213.4,43.15 CN1.187
  BOTTOM w0.127: v1(214.01,43.75) 213.63,44.14 212.74,44.14 212.25,44.63 212.25,45.48 212.13,45.6 211.84,45.6 211.73,45.71 211.73,45.94 211.84,46.05 212.13,46.05 212.25,46.17 212.25,46.4 212.13,46.51 211.84,46.51 211.73,46.63 211.73,46.85 211.84,46.97 212.13,46.97 212.25,47.08 212.25,47.31 212.13,47.43 211.84,47.43 211.73,47.54 211.73,47.77 211.84,47.88 212.13,47.88 212.25,48 212.25,48.23 212.13,48.34 211.84,48.34 211.73,48.45 211.73,48.68 211.84,48.8 212.13,48.8 212.25,48.91 212.25,49.14 212.13,49.25 211.84,49.25 211.73,49.37 211.73,49.6 211.84,49.71 212.13,49.71 212.25,49.83 212.25,50.06 212.13,50.17 211.84,50.17 211.73,50.28 211.73,50.51 211.84,50.63 212.12,50.63 212.23,50.74 212.23,51.5 211.99,51.74 210.87,51.74 198.82,63.79 198.54,63.79 v1(198.01,64.33)
M_A_DQ0: length 51.4
  TOP w0.102: v1(185.82,77.28) 186.46,76.64 186.46,75.73 186.3,75.58 186.3,75.26 186.33,75.24 186.33,75.22 186.39,75.16 186.39,74.92 186.29,74.82 186.29,74.53 U1.AK51
  TOP w0.127: CN1.4 217.66,100.45 v1(217.06,99.85)
  BOTTOM w0.127: v1(185.82,77.28) 186.21,77.68 186.21,78.89 186.17,78.93 186.17,80.64 187.85,82.32 187.85,83.72 193.47,89.35 204.49,89.35 210.33,95.19 210.33,97.09 211.99,98.75 215.28,98.75 215.41,98.88 215.41,99.63 215.62,99.85 v1(217.06,99.85)
M_A_DQ1: length 50.6
  TOP w0.102: U1.AL51 186.78,74.87 186.78,75.16 186.86,75.24 186.86,77.51 185.88,78.49
  TOP w0.114: 185.88,78.49 v1(185.82,78.55)
  TOP w0.127: v1(214.77,99.55) 214.31,100.01 213.13,100.01 213,100.15 CN1.5
  BOTTOM w0.127: v1(185.82,78.55) 185.73,78.64 185.73,80.74 187.47,82.48 187.47,83.89 193.31,89.73 194.08,89.73 194.21,89.86 194.21,90.23 194.35,90.36 194.54,90.36 194.67,90.23 194.67,89.86 194.81,89.73 195,89.73 195.13,89.86 195.13,90.23 195.26,90.36 195.45,90.36 195.59,90.23 195.59,89.86 195.72,89.73 204.11,89.73 209.82,95.44 209.82,97.35 211.6,99.13 214.36,99.13 v1(214.77,99.55)
M_A_DQ2: length 50.5
  TOP w0.102: U1.AT52 189.12,75.14 189.12,76.14 v1(189.5,76.52)
  TOP w0.127: CN1.15 212.74,97.15 213.18,96.71 213.68,96.71 214.06,96.33 215.02,96.33 v1(215.54,95.82)
  BOTTOM w0.127: v1(215.54,95.82) 215.02,96.33 213.12,96.33 212.62,95.82 212.62,94.42 211.41,93.22 211.41,88.24 211.24,88.08 211,88.08 210.84,88.24 210.84,88.94 210.69,89.09 210.48,89.09 210.33,88.94 210.33,87.82 209.69,87.19 194.29,87.19 190.22,83.12 190.22,81.81 188.33,79.92 188.33,77.69 v1(189.5,76.52)
M_A_DQ3: length 53
  TOP w0.102: v1(189.5,77.15) 188.89,76.54 188.89,75.32 188.72,75.16 188.72,74.87 U1.AR51
  TOP w0.127: CN1.17 212.72,96.55 212.93,96.33 213.5,96.33 v1(214.01,95.82)
  BOTTOM w0.127: v1(214.01,95.82) 214.52,95.32 215.64,95.32 215.84,95.11 215.84,93.33 215.66,93.16 215.33,93.16 215.2,93.29 215.2,93.91 215.07,94.05 214.88,94.05 214.74,93.91 214.74,93.29 214.61,93.16 214.42,93.16 214.29,93.29 214.29,94.04 214.15,94.17 213.96,94.17 213.83,94.04 213.83,93.29 213.69,93.16 213.5,93.16 213.37,93.29 213.37,93.91 213.24,94.05 212.79,94.05 211.84,93.09 211.84,87.93 210.71,86.81 194.55,86.81 190.66,82.91 190.66,81.71 188.71,79.76 188.71,77.94 v1(189.5,77.15)
M_A_DQ4: length 51.7
  TOP w0.102: v1(185.82,77.92) 186.66,77.08 186.66,75.5 U1.AL53
  TOP w0.127: v1(213.25,99.55) CN1.7
  BOTTOM w0.127: v1(213.25,99.55) 211.38,99.55 209.31,97.47 209.31,95.57 204.61,90.87 201.47,90.87 201.34,90.74 201.34,90.5 201.21,90.36 201.02,90.36 200.88,90.5 200.88,90.74 200.75,90.87 200.56,90.87 200.43,90.74 200.43,90.37 200.29,90.24 200.1,90.24 199.97,90.37 199.97,90.74 199.83,90.87 199.65,90.87 199.51,90.74 199.51,90.24 199.38,90.11 199.19,90.11 199.05,90.24 199.05,90.74 198.92,90.87 198.73,90.87 198.6,90.74 198.6,90.24 198.46,90.11 198.27,90.11 198.14,90.24 198.14,90.74 198.01,90.87 197.82,90.87 197.68,90.74 197.68,90.24 197.55,90.11 197.36,90.11 197.23,90.24 197.23,90.74 197.09,90.87 196.9,90.87 196.77,90.74 196.77,90.24 196.63,90.11 196.44,90.11 196.31,90.24 196.31,90.74 196.18,90.87 193.87,90.87 187.09,84.09 187.09,82.64 185.31,80.86 185.31,78.42 v1(185.82,77.92)
M_A_DQ5: length 49.3
  TOP w0.102: v1(185.82,76.65) 186.25,76.21 186.25,75.82 186.1,75.67 186.1,75.04 U1.AK52
  TOP w0.127: CN1.6 v1(218.58,99.85)
  BOTTOM w0.127: v1(185.82,76.65) 186.58,77.41 186.58,80.51 188.25,82.18 188.25,83.58 193.63,88.97 204.69,88.97 210.84,95.11 210.84,96.89 212.37,98.42 216.24,98.42 217.13,99.3 218.04,99.3 v1(218.58,99.85)
M_A_DQ6: length 52.8
  TOP w0.102: U1.AR53 188.68,75.58 188.68,76.97 v1(189.5,77.79)
  TOP w0.127: CN1.16 v1(218.58,96.85)
  BOTTOM w0.127: v1(218.58,96.85) 217.99,96.26 216.43,96.26 216.23,96.07 216.23,92.8 215.57,92.13 215.57,91.26 215.44,91.12 215.25,91.12 215.11,91.26 215.11,92.01 214.98,92.14 214.79,92.14 214.65,92.01 214.65,91.26 214.52,91.12 214.33,91.12 214.2,91.26 214.2,92.01 214.06,92.14 213.87,92.14 213.74,92.01 213.74,91.26 213.61,91.12 213.42,91.12 213.28,91.26 213.28,91.81 213.08,92.01 212.44,92.01 212.23,91.81 212.23,87.7 210.96,86.43 194.73,86.43 191.08,82.77 191.08,81.6 189.09,79.62 189.09,78.2 v1(189.5,77.79)
